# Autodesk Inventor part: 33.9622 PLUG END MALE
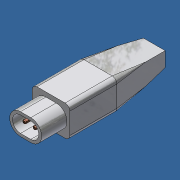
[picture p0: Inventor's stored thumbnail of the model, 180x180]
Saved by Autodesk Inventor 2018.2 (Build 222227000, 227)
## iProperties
Created: 2017-10
Part Number: 33.9622 PLUG END MALE
Material: Generic
Document SubType Name: Modeling
Designer: Admin
Density: 1 g/cm^3
Appearance: Snow
Author: Admin
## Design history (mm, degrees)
workplane "Work Plane9"
sketch "Sketch3"
  geometry: L1 (-2.2, -12.732)-(2.2, -12.732); L2 (2.2, -21.932)-(-2.2, -21.932); L3 (2.2, -13.932)-(-2.2, -13.932); L4 (-2.2, -20.732)-(2.2, -20.732); A1 r 4.6 centre (-2.2, -17.332) between (-2.2, -12.732) and (-2.2, -21.932); A2 r 4.6 centre (2.2, -17.332) between (2.2, -21.932) and (2.2, -12.732); A3 r 3.4 centre (-2.2, -17.332) between (-2.2, -13.932) and (-2.2, -20.732); A4 r 3.4 centre (2.2, -17.332) between (2.2, -20.732) and (2.2, -13.932); 2 further points
  constraints: 8 end point, 8 point on circle, 4 centre point, 2 parallel, 2 tangent, 1 equal radius, 1 horizontal, 1 horizontal alignment, 1 midpoint, 1 vertical alignment, 3 other
  dimensions: "d11" = 9.2 distance between parallel lines of L2 L1; "d12" = 13.6 dimension on A2 A1; "d13" = 1.2 distance between parallel lines of L3 L1
extrude "Extrusion3" join sketch "Sketch3" distance "d14" = 10.8; taper "d15" = 0 deg
workplane "Work Plane5"
sketch "Sketch4"
  geometry: C1 r 0.75 at (-2.2, -17.332); C2 r 0.75 at (2.2, -17.332); 1 further point
  constraints: 2 centre point, 1 equal radius
  dimensions: "d16" = 1.5 diameter of C2
extrude "Extrusion4" join sketch "Sketch4" distance "d17" = 9.4; taper "d18" = 0 deg
fillet "Fillet3" dims "d37" = 0.5
sketch "Sketch8"
  geometry: L1 (-8, -10.832)-(8, -10.832); L2 (8, -10.832)-(8, -23.832); L3 (8, -23.832)-(-8, -23.832); L4 (-8, -23.832)-(-8, -10.832); L5 (-2.2, -17.332)-(2.2, -17.332); C1 r 0.75 at (-2.2, -17.332) reference; C2 r 0.75 at (2.2, -17.332) reference; A1 r 3.4 centre (2.2, -17.332) between (2.2, -20.732) and (2.2, -13.932) reference; 4 further points
  constraints: 10 end point, 3 midpoint, 2 horizontal, 2 parallel, 1 horizontal alignment, 1 perpendicular, 1 vertical alignment
  dimensions: "d38" = 16 distance of L1.start L1.end; "d39" = 13 distance of L1.end L2.end
extrude "Extrusion8" join sketch "Sketch8" distance "d40" = 20; taper "d41" = 0 deg
fillet "Fillet4" dims "d42" = 2
sketch "Sketch9"
  geometry: L1 (8, -21.832)-(8, -12.832) reference; L2 (6, -10.832)-(-6, -10.832) reference; L3 (-8, -12.832)-(-8, -21.832) reference; L4 (-6, -23.832)-(6, -23.832) reference; A1 r 2 centre (6, -21.832) between (6, -23.832) and (8, -21.832) reference; A2 r 2 centre (6, -12.832) between (8, -12.832) and (6, -10.832) reference; A3 r 2 centre (-6, -12.832) between (-6, -10.832) and (-8, -12.832) reference; A4 r 2 centre (-6, -21.832) between (-8, -21.832) and (-6, -23.832) reference; 1 further point
extrude "Extrusion9" join sketch "Sketch9" distance "d43" = 24; taper "d44" = -8 deg
sketch "Sketch10"
  geometry: L1 (4.627, -14.205)-(4.627, -20.459) reference; L2 (-4.627, -14.205)-(4.627, -14.205) reference; L3 (-3.5, -18.982)-(3.5, -18.982); L4 (3.5, -18.982)-(3.5, -15.682); L5 (3.5, -15.682)-(-3.5, -15.682); L6 (-3.5, -15.682)-(-3.5, -18.982); 5 further points
  constraints: 8 end point, 4 midpoint, 2 parallel, 1 horizontal, 1 horizontal alignment, 1 perpendicular, 1 vertical alignment
  dimensions: "d45" = 3.3 distance of L3.end L4.end; "d46" = 7 distance of L4.end L5.end
extrude "Extrusion10" cut sketch "Sketch10" distance "d47" = 0.1; taper "d48" = 0 deg
body "Solid1"
